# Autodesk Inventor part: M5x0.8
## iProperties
IsCustomPart: 0
Manager: KYOUNG IL JANG
Company: 한국ATC센터
Created: 2009-02
Part Number: M5x0.8
Material: Steel, Mild
Description: 6각머리 태핑 나사
Document SubType Name: Modeling
Standard: KS B 1003
Standards Organization: KS
Language: ko-KR
Size Designation: M 5 x 20
Categories: <MemberInstance><Categories><Category DisplayName="조임쇠" InternalName="e4da775c-781d-43d5-af7c-5136215cf5a6" Mnemonic="FSTN"><Category DisplayName="볼트" InternalN
Density: 1 g/cm^3
Checked By: KYOUNG IL JANG
Vendor: CBT Solutions
Designer: KYOUNG IL JANG
Author: KYOUNG IL JANG
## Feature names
1. Fillet2
